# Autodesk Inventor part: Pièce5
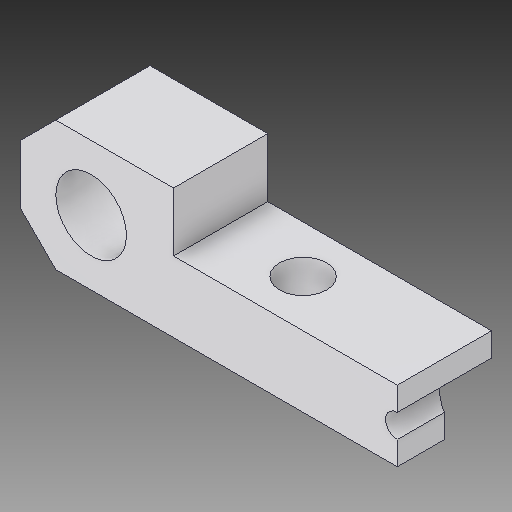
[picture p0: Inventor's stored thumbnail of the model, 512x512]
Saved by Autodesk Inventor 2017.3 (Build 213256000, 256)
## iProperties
Created: 2007-11
Part Number: Pièce5
Material: solidworks materials|Alliage 7079|22
Document SubType Name: Modeling
Designer: ficho
Density: 2.7 g/cm^3
Appearance: 227,227,233
Author: ficho
Sending System: SolidWorks 2009
Last Author: christophe
Last Saved: 2011-01-20
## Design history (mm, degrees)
feature "Chanfrein1"
node "Solide1"
